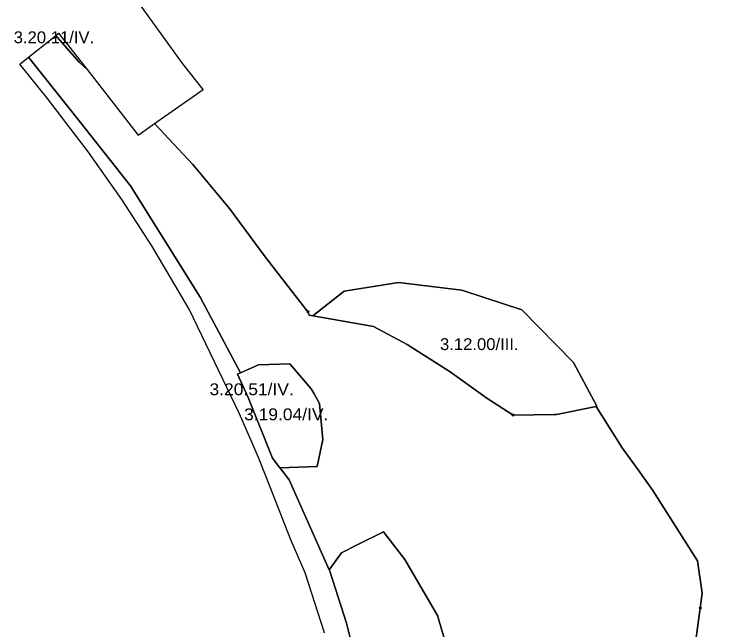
# Model space of a CAD drawing. Extents: x -650455 to -642254, y -1075222 to -1066610.
# Drawn here: x -649645 to -649039, y -1068135 to -1067615 of the extents above; entities that cross this region are included whole.
import ezdxf
from ezdxf.enums import TextEntityAlignment as Align

# ---------------------------------------------------------------- set-up
doc = ezdxf.new("R2010")
doc.units = 0
doc.header["$LTSCALE"] = 4
doc.header["$PDMODE"] = 32
doc.header["$PDSIZE"] = 2
for name, color, linetype, lineweight in [('1', 7, 'Continuous', 25), ('11', 7, 'Continuous', 13), ('13', 7, 'Continuous', 13), ('14', 7, 'Continuous', 13)]:
    doc.layers.add(name, color=color, linetype=linetype, lineweight=lineweight)
doc.layers.add('2', color=7, linetype='Continuous')

msp = doc.modelspace()

# ---------------------------------------------------------------- linework, layer by layer
at = {"layer": '1'}
for points in [[(-649072.632, -1068166.715), (-649065.71, -1068116.69), (-649063.97, -1068104.117), (-649067.907, -1068076.753), (-649105.703, -1068017.306), (-649118.254, -1068000), (-649131.687, -1067981.479), (-649153.622, -1067946.381), (-649152.947, -1067946.243), (-649172.632, -1067909.235), (-649216.333, -1067864.747), (-649248.33, -1067854.452), (-649267.12, -1067848.408), (-649320.663, -1067841.715), (-649366.332, -1067849.194), (-649392.871, -1067869.916), (-649395.937, -1067869.389), (-649397.041, -1067866.517), (-649433.262, -1067820.062), (-649463.183, -1067779.314), (-649494.285, -1067742.306), (-649526.491, -1067707.538), (-649485.652, -1067678.963), (-649502.696, -1067657.083), (-649561.33, -1067575.772)], [(-649487.986, -1067854.313), (-649547.042, -1067760.218), (-649589.168, -1067706.675), (-649633.089, -1067651.521), (-649613.165, -1067635.713), (-649608.96, -1067634.549), (-649590.348, -1067655.691), (-649583.592, -1067662.064)], [(-649383.086, -1068137.741), (-649399.254, -1068087.078), (-649411.404, -1068059.031), (-649429.146, -1068013.857), (-649438.69, -1067989.557), (-649454.92, -1067952.581), (-649497.258, -1067864.235), (-649528.871, -1067810.89), (-649554.132, -1067771.798), (-649582.358, -1067731.859), (-649617.075, -1067686.416), (-649640.501, -1067657.401), (-649639.049, -1067656.25), (-649633.089, -1067651.521), (-649589.168, -1067706.675), (-649547.042, -1067760.218), (-649487.986, -1067854.313), (-649476.79, -1067875.337), (-649454.049, -1067918.042), (-649456.626, -1067919.162), (-649447.5, -1067939), (-649427, -1067990.001), (-649420.659, -1067998.379), (-649419.432, -1068000.001), (-649413, -1068008.5), (-649379.015, -1068084.351), (-649378.5, -1068085.5), (-649364.5, -1068129.5), (-649354, -1068171.001)], [(-649583.592, -1067662.064), (-649540.475, -1067717.322), (-649526.491, -1067707.538), (-649494.285, -1067742.306), (-649463.183, -1067779.314), (-649433.262, -1067820.062), (-649397.041, -1067866.517), (-649395.937, -1067869.389), (-649392.871, -1067869.916), (-649370.27, -1067873.801), (-649341.529, -1067878.919), (-649313.183, -1067894.274), (-649276.962, -1067917.108), (-649245.86, -1067939.55), (-649223.813, -1067953.722), (-649188.725, -1067953.345), (-649187.199, -1067953.329), (-649153.622, -1067946.381), (-649131.687, -1067981.479), (-649118.254, -1068000), (-649105.703, -1068017.306), (-649067.907, -1068076.753), (-649063.97, -1068104.117), (-649065.71, -1068116.69), (-649072.632, -1068166.715)], [(-649279.725, -1068149.82), (-649287.592, -1068123.014), (-649315.151, -1068075.573), (-649333.262, -1068052.344), (-649355.332, -1068063.38), (-649368.695, -1068070.06), (-649379.015, -1068084.351), (-649413, -1068008.5), (-649419.432, -1068000.001), (-649420.659, -1067998.379), (-649389.167, -1067997.226), (-649384.443, -1067974.393), (-649387.198, -1067944.077), (-649391.837, -1067935.83), (-649394.285, -1067931.479), (-649412.395, -1067910.613), (-649438.773, -1067911.399), (-649454.049, -1067918.042), (-649476.79, -1067875.337), (-649487.986, -1067854.313)], [(-649354, -1068171.001), (-649364.5, -1068129.5), (-649378.5, -1068085.5), (-649379.015, -1068084.351), (-649368.695, -1068070.06), (-649355.332, -1068063.38), (-649333.262, -1068052.344), (-649315.151, -1068075.573), (-649287.592, -1068123.014), (-649279.725, -1068149.82)]]:
    msp.add_lwpolyline(points, dxfattribs=at)
for points in [[(-649607.599, -1067631.297), (-649583.592, -1067662.064), (-649590.348, -1067655.691), (-649608.96, -1067634.549), (-649609.962, -1067633.173)], [(-649608.96, -1067634.549), (-649613.165, -1067635.713), (-649609.962, -1067633.173)], [(-649153.622, -1067946.381), (-649187.199, -1067953.329), (-649188.725, -1067953.345), (-649223.813, -1067953.722), (-649245.86, -1067939.55), (-649276.962, -1067917.108), (-649313.183, -1067894.274), (-649341.529, -1067878.919), (-649370.27, -1067873.801), (-649392.871, -1067869.916), (-649366.332, -1067849.194), (-649320.663, -1067841.715), (-649267.12, -1067848.408), (-649248.33, -1067854.452), (-649216.333, -1067864.747), (-649172.632, -1067909.235), (-649152.947, -1067946.243)], [(-649420.659, -1067998.379), (-649427, -1067990.001), (-649447.5, -1067939), (-649456.626, -1067919.162), (-649454.049, -1067918.042), (-649438.773, -1067911.399), (-649412.395, -1067910.613), (-649394.285, -1067931.479), (-649391.837, -1067935.83), (-649387.198, -1067944.077), (-649384.443, -1067974.393), (-649389.167, -1067997.226)]]:
    msp.add_lwpolyline(points, close=True, dxfattribs=at)
at = {"layer": '11'}
for points in [[(-649561.33, -1067575.772), (-649502.696, -1067657.083), (-649485.652, -1067678.963), (-649526.491, -1067707.538), (-649494.285, -1067742.306), (-649463.183, -1067779.314), (-649433.262, -1067820.062), (-649397.041, -1067866.517), (-649395.937, -1067869.389), (-649392.871, -1067869.916), (-649366.332, -1067849.194)], [(-649366.332, -1067849.194), (-649320.663, -1067841.715), (-649267.12, -1067848.408), (-649248.33, -1067854.452), (-649216.333, -1067864.747), (-649172.632, -1067909.235), (-649152.947, -1067946.243), (-649153.622, -1067946.381), (-649131.687, -1067981.479), (-649118.254, -1068000), (-649105.703, -1068017.306), (-649067.907, -1068076.753), (-649063.97, -1068104.117), (-649065.71, -1068116.69), (-649072.632, -1068166.715), (-649072.238, -1068220.849), (-649063.183, -1068247.029), (-649039.167, -1068274.588)]]:
    msp.add_lwpolyline(points, dxfattribs=at)
at = {"layer": '13'}
msp.add_line((-649072.632, -1068166.715), (-649065.71, -1068116.69), dxfattribs=at)
for points in [[(-649397.041, -1067866.517), (-649433.262, -1067820.062), (-649463.183, -1067779.314), (-649494.285, -1067742.306), (-649526.491, -1067707.538), (-649540.475, -1067717.322), (-649583.592, -1067662.064), (-649590.348, -1067655.691), (-649608.96, -1067634.549), (-649613.165, -1067635.713), (-649633.089, -1067651.521), (-649589.168, -1067706.675), (-649547.042, -1067760.218), (-649487.986, -1067854.313), (-649476.79, -1067875.337), (-649454.049, -1067918.042), (-649438.773, -1067911.399), (-649412.395, -1067910.613), (-649394.285, -1067931.479), (-649391.837, -1067935.83), (-649387.198, -1067944.077), (-649384.443, -1067974.393), (-649389.167, -1067997.226), (-649420.659, -1067998.379), (-649419.432, -1068000.001), (-649413, -1068008.5), (-649379.015, -1068084.351), (-649368.695, -1068070.06), (-649355.332, -1068063.38), (-649333.262, -1068052.344), (-649315.151, -1068075.573), (-649287.592, -1068123.014), (-649279.725, -1068149.82)], [(-649223.813, -1067953.722), (-649245.86, -1067939.55), (-649276.962, -1067917.108), (-649313.183, -1067894.274), (-649341.529, -1067878.919), (-649370.27, -1067873.801), (-649392.871, -1067869.916), (-649395.937, -1067869.389), (-649397.041, -1067866.517)], [(-649065.71, -1068116.69), (-649063.97, -1068104.117), (-649067.907, -1068076.753), (-649105.703, -1068017.306), (-649118.254, -1068000), (-649131.687, -1067981.479), (-649153.622, -1067946.381), (-649187.199, -1067953.329), (-649188.725, -1067953.345), (-649223.813, -1067953.722)]]:
    msp.add_lwpolyline(points, dxfattribs=at)
msp.add_lwpolyline([(-649223.813, -1067953.722), (-649188.725, -1067953.345), (-649187.199, -1067953.329), (-649153.622, -1067946.381), (-649152.947, -1067946.243), (-649172.632, -1067909.235), (-649216.333, -1067864.747), (-649248.33, -1067854.452), (-649267.12, -1067848.408), (-649320.663, -1067841.715), (-649366.332, -1067849.194), (-649392.871, -1067869.916), (-649370.27, -1067873.801), (-649341.529, -1067878.919), (-649313.183, -1067894.274), (-649276.962, -1067917.108), (-649245.86, -1067939.55)], close=True, dxfattribs=at)
for p in [(-649397.041, -1067866.517), (-649223.813, -1067953.722), (-649065.71, -1068116.69)]:
    msp.add_point(p, dxfattribs=at)
at = {"layer": '14'}
for points in [[(-649590.348, -1067655.691), (-649583.592, -1067662.064), (-649607.599, -1067631.297), (-649609.962, -1067633.173), (-649608.96, -1067634.549)], [(-649389.167, -1067997.226), (-649384.443, -1067974.393), (-649387.198, -1067944.077), (-649391.837, -1067935.83), (-649394.285, -1067931.479), (-649412.395, -1067910.613), (-649438.773, -1067911.399), (-649454.049, -1067918.042), (-649456.626, -1067919.162), (-649447.5, -1067939), (-649427, -1067990.001), (-649420.659, -1067998.379)]]:
    msp.add_lwpolyline(points, close=True, dxfattribs=at)
for points in [[(-649354, -1068171.001), (-649364.5, -1068129.5), (-649378.5, -1068085.5), (-649379.015, -1068084.351), (-649413, -1068008.5), (-649419.432, -1068000.001), (-649420.659, -1067998.379), (-649427, -1067990.001), (-649447.5, -1067939), (-649456.626, -1067919.162), (-649454.049, -1067918.042), (-649476.79, -1067875.337), (-649487.986, -1067854.313), (-649547.042, -1067760.218), (-649589.168, -1067706.675), (-649633.089, -1067651.521), (-649639.049, -1067656.25), (-649640.501, -1067657.401), (-649617.075, -1067686.416), (-649582.358, -1067731.859), (-649554.132, -1067771.798), (-649528.871, -1067810.89), (-649497.258, -1067864.235), (-649454.92, -1067952.581), (-649438.69, -1067989.557), (-649429.146, -1068013.857), (-649411.404, -1068059.031), (-649399.254, -1068087.078), (-649383.086, -1068137.741)], [(-649279.725, -1068149.82), (-649287.592, -1068123.014), (-649315.151, -1068075.573), (-649333.262, -1068052.344), (-649355.332, -1068063.38), (-649368.695, -1068070.06), (-649379.015, -1068084.351), (-649378.5, -1068085.5), (-649364.5, -1068129.5), (-649354, -1068171.001), (-649335.143, -1068255.857)]]:
    msp.add_lwpolyline(points, dxfattribs=at)

# ---------------------------------------------------------------- texts
at = {"layer": '2'}
for s, width, p in [('3.20.11/IV.', 1.05, (-649611.583, -1067639.741)), ('3.12.00/III.', 1.05, (-649252.304, -1067898.859)), ('3.20.51/IV.', 1.1, (-649444.582, -1067936.954)), ('3.19.04/IV.', 1.1, (-649415.372, -1067958.119))]:
    msp.add_text(s, height=10, dxfattribs=dict(at, width=width)).set_placement(p, align=Align.CENTER)

doc.saveas('drawing.dxf')
